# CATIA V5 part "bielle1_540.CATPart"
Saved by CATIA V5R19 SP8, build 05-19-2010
Part number: elt1
Bounding box of the stored display mesh (mm): x -20 to 20, y 0 to 20, z -86.667 to 86.667
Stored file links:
  D:\Dropbox\CIAO82010_JCF\VIGUIER\0540-VIGUIER\CAO\bielle1_540.CATPart
  D:\Dropbox\CIAO82010_JCF\VIGUIER\0540-VIGUIER\CAO\0540.CATProduct
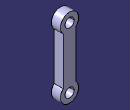
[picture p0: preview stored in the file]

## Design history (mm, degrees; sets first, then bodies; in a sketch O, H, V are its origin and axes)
External parameters (linked from other documents)
  External.longueur_bielles = 200 mm
  External.rayon_assemblage = 10 mm
AxisSystem1: origin (0, 0, 0), X (1, 0, 0), Y (0, 1, 0), Z (0, 0, 1)
Body1 (main body)
  Sketch1 on ZX plane of AxisSystem1, origin (0, 0, 0), H (0, 0, 1), V (1, 0, 0)
    arc A1 centre (-66.6667, 0) radius 20 from (-52.2391, 13.8508) to (-52.2391, -13.8508) ccw
    point P1 (-66.6667, 0)
    point P2 (-52.2391, 13.8508)
    point P3 (-52.2391, -13.8508)
    arc A2 centre (66.6667, 0) radius 20 from (52.214, -13.8247) to (52.214, 13.8247) ccw
    point P4 (66.6667, 0)
    point P5 (52.214, -13.8247)
    point P6 (52.214, 13.8247)
    line L1 (-52.2391, 13.8508) -> (52.214, 13.8247)
    line L2 (-52.2391, -13.8508) -> (52.214, -13.8247)
    radius A2 = 20 {= 2*External.rayon_assemblage}
    radius A1 = 20 {= 2*External.rayon_assemblage}
    distance P4 P1 = 133.3333 {= External.longueur_bielles /1.5}
    coincidence: P1 H, P4 H
    symmetry: P1 P4 V, P2 P3 H, P6 P5 H
  Pad1: profile Sketch1, direction (0, 1, 0), length 20
  Sketch2 on start face of Pad1, origin (0, 0, 0), H (1, 0, 0), V (0, 0, 1)
    circle A1 centre (0, 66.6667) radius 10
    point P1 (0, 66.6667)
    reference projected arc E1 centre (0, 66.6667) radius 20 from (13.8247, 52.214) to (-13.8247, 52.214) ccw from edge [start face of Pad1 | face of Pad1 from Sketch1.A2]
    circle A2 centre (0, -66.6667) radius 10
    radius A1 = 10 {= External.rayon_assemblage}
    coincidence: P1 V
    concentricity: P1 E1
    symmetry: A1 A2 H
  Pocket1: profile Sketch2, direction (0, 1, 0), through (limit type 3)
